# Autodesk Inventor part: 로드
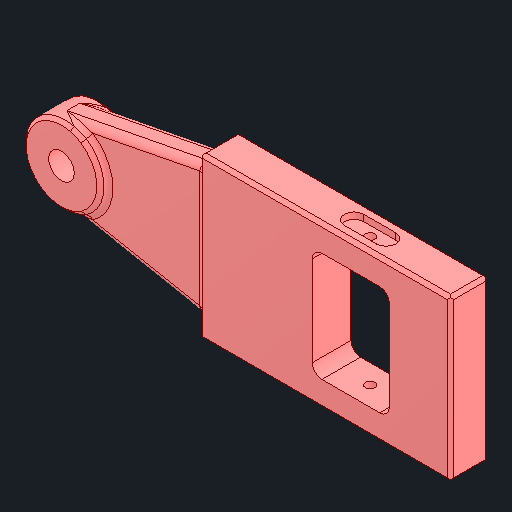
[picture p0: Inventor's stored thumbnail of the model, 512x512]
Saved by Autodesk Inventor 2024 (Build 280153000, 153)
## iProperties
Created: 2025-02
Part Number: 로드
Material: 강철, 탄소
Document SubType Name: Modeling
Designer: kh_501
Density: 7.85 g/cm^3
Appearance: 기본값
Author: jhkim
Sending System: Autodesk Inventor 2025
Preprocessor: ST-DEVELOPER v20
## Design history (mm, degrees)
feature "솔리드1"
node "솔리드2"
